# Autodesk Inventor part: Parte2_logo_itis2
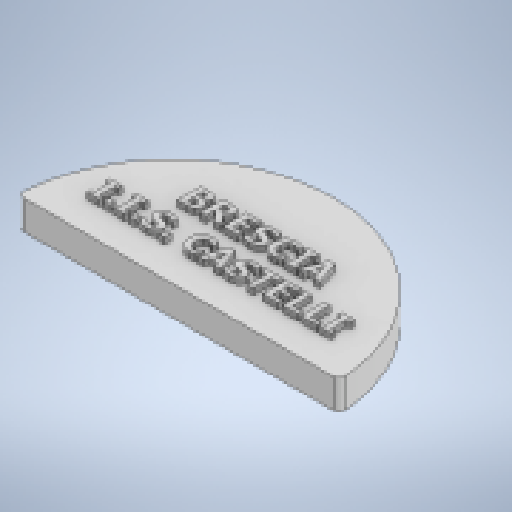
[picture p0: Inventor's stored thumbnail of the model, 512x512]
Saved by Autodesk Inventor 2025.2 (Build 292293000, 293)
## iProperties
Created: 2025-03
Part Number: Parte2_logo_itis2
Material: Generico
Document SubType Name: Modeling
Designer: 18907419
Density: 1 g/cm^3
Appearance: Default
Author: 18907419
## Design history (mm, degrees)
sketch "Schizzo1"
  geometry: L1 (0, 0)-(198.619, 0); L2 (198.619, 0)-(198.619, -200); L3 (198.619, -200)-(0, -200); L4 (0, -200)-(0, 0); 1 other entity
  constraints: 2 other
  dimensions: "d1" = 200 distance of L3.end L1.start
  node "Immagine1"
sketch "Schizzo2" dims "d13" = 110
  geometry: L1 (105.821, -199.217)-(91.821, -199.217); L2 (91.821, -199.217)-(89.861, -182.291); L3 (98.821, -199.217)-(98.821, -182.907); L4 (105.821, -199.217)-(107.782, -182.291); L5 (143.188, -189.466)-(130.253, -194.824); L6 (130.253, -194.824)-(121.965, -179.936); L7 (136.721, -192.145)-(130.479, -177.077); L8 (143.188, -189.466)-(138.521, -173.078); L9 (173.978, -166.158)-(164.079, -176.058); L10 (164.079, -176.058)-(150.724, -165.475); L11 (169.028, -171.108)-(157.495, -159.575); L12 (173.978, -166.158)-(163.395, -152.804); L13 (193.505, -132.842)-(188.148, -145.776); L14 (188.148, -145.776)-(171.76, -141.109); L15 (190.826, -139.309)-(175.758, -133.067); L16 (193.505, -132.842)-(178.617, -124.553); L17 (198.796, -94.588)-(198.796, -108.588); L18 (198.796, -108.588)-(181.87, -110.548); L19 (198.796, -101.588)-(182.486, -101.588); L20 (198.796, -94.588)-(181.87, -92.628); L21 (189.045, -57.222)-(194.403, -70.156); L22 (194.403, -70.156)-(179.515, -78.445); L23 (191.724, -63.689)-(176.655, -69.931); L24 (189.045, -57.222)-(172.657, -61.888); L25 (165.737, -26.431)-(175.637, -36.331); L26 (175.637, -36.331)-(165.054, -49.686); L27 (170.687, -31.381)-(159.154, -42.914); L28 (165.737, -26.431)-(152.382, -37.014); L29 (132.42, -6.904)-(145.355, -12.262); L30 (145.355, -12.262)-(140.688, -28.65); L31 (138.888, -9.583)-(132.646, -24.652); L32 (132.42, -6.904)-(124.132, -21.792); L33 (94.167, -1.614)-(108.167, -1.614); L34 (108.167, -1.614)-(110.127, -18.54); L35 (101.167, -1.614)-(101.167, -17.924); L36 (94.167, -1.614)-(92.207, -18.54); L37 (56.801, -11.364)-(69.735, -6.007); L38 (69.735, -6.007)-(78.023, -20.895); L39 (63.268, -8.686)-(69.51, -23.754); L40 (56.801, -11.364)-(61.467, -27.753); L41 (26.01, -34.672)-(35.91, -24.773); L42 (35.91, -24.773)-(49.265, -35.356); L43 (30.96, -29.723)-(42.493, -41.256); L44 (26.01, -34.672)-(36.593, -48.027); L45 (6.483, -67.989)-(11.841, -55.055); L46 (11.841, -55.055)-(28.229, -59.721); L47 (9.162, -61.522)-(24.231, -67.764); L48 (6.483, -67.989)-(21.371, -76.278); L49 (1.192, -106.243)-(1.192, -92.243); L50 (1.192, -92.243)-(18.119, -90.283); L51 (1.192, -99.243)-(17.503, -99.243); L52 (1.192, -106.243)-(18.119, -108.203); L53 (10.943, -143.609)-(5.586, -130.675); L54 (5.586, -130.675)-(20.474, -122.386); L55 (8.264, -137.142)-(23.333, -130.9); L56 (10.943, -143.609)-(27.331, -138.942); L57 (34.251, -174.399)-(24.352, -164.5); L58 (24.352, -164.5)-(34.935, -151.145); L59 (29.301, -169.45)-(40.835, -157.917); L60 (34.251, -174.399)-(47.606, -163.816); L61 (67.568, -193.926)-(54.634, -188.569); L62 (54.634, -188.569)-(59.3, -172.181); L63 (61.101, -191.248)-(67.343, -176.179); L64 (67.568, -193.926)-(75.856, -179.038)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; A1 r 82.5 centre (99.994, -100.415) between (89.861, -182.291) and (98.821, -182.907); A2 r 80 centre (81.89, -116.945) between (124.568, -184.611) and (153.002, -80.297); A3 r 85 centre (79.253, -82.612) between (32.823, -153.81) and (129.534, -151.145); A4 r 61.843 centre (94.454, -100.214) between (129.534, -151.145) and (153.002, -80.297); 10 further points
  constraints: 134 end point, 9 point on circle, 4 centre point, 4 horizontal, 2 point on line, 1 coincident, 1 midpoint, 1 parallel, 1 symmetric about line, 1 vertical, 164 other
  dimensions: "d2" = 165 diameter of A1; "d3" = 14 distance of L1.start L1.end; "d6" = 360 deg dimension on A1.centre L1.start (derived); "d8" = 80 radius of A2; "d14" = 2 distance between parallel lines of L65 L66
extrude "Estrusione2" new body sketch "Schizzo2" distance "d15" = 10; taper "d16" = 0 deg
fillet "Raccordo1" dims "d17" = 2
sketch "Schizzo3"
  geometry: L1 (-152.766, 134.17)-(-47.28, 134.17); L2 (-47.28, 134.17)-(-47.28, 107.316); L3 (-47.28, 107.316)-(-152.766, 107.316); L4 (-152.766, 107.316)-(-152.766, 134.17); 1 further point
  constraints: 2 other
extrude "Estrusione3" join sketch "Schizzo3" distance "d18" = 2; taper "d19" = 0 deg
node "Solido2"
node "Schizzo - Serie circolare1" dims "d6" = 360 deg (derived)
